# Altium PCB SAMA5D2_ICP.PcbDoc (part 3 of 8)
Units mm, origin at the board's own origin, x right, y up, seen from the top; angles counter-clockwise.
Board outline 150 x 100 mm, 6 copper layers (L1 - TOP, L2 - GND, L3 - SIG, L4 - SIG, L5 - VCC, L6 - BOT), stack 1.512 mm thick; 708 components, 597 nets, 2710 pads, 1437 vias.
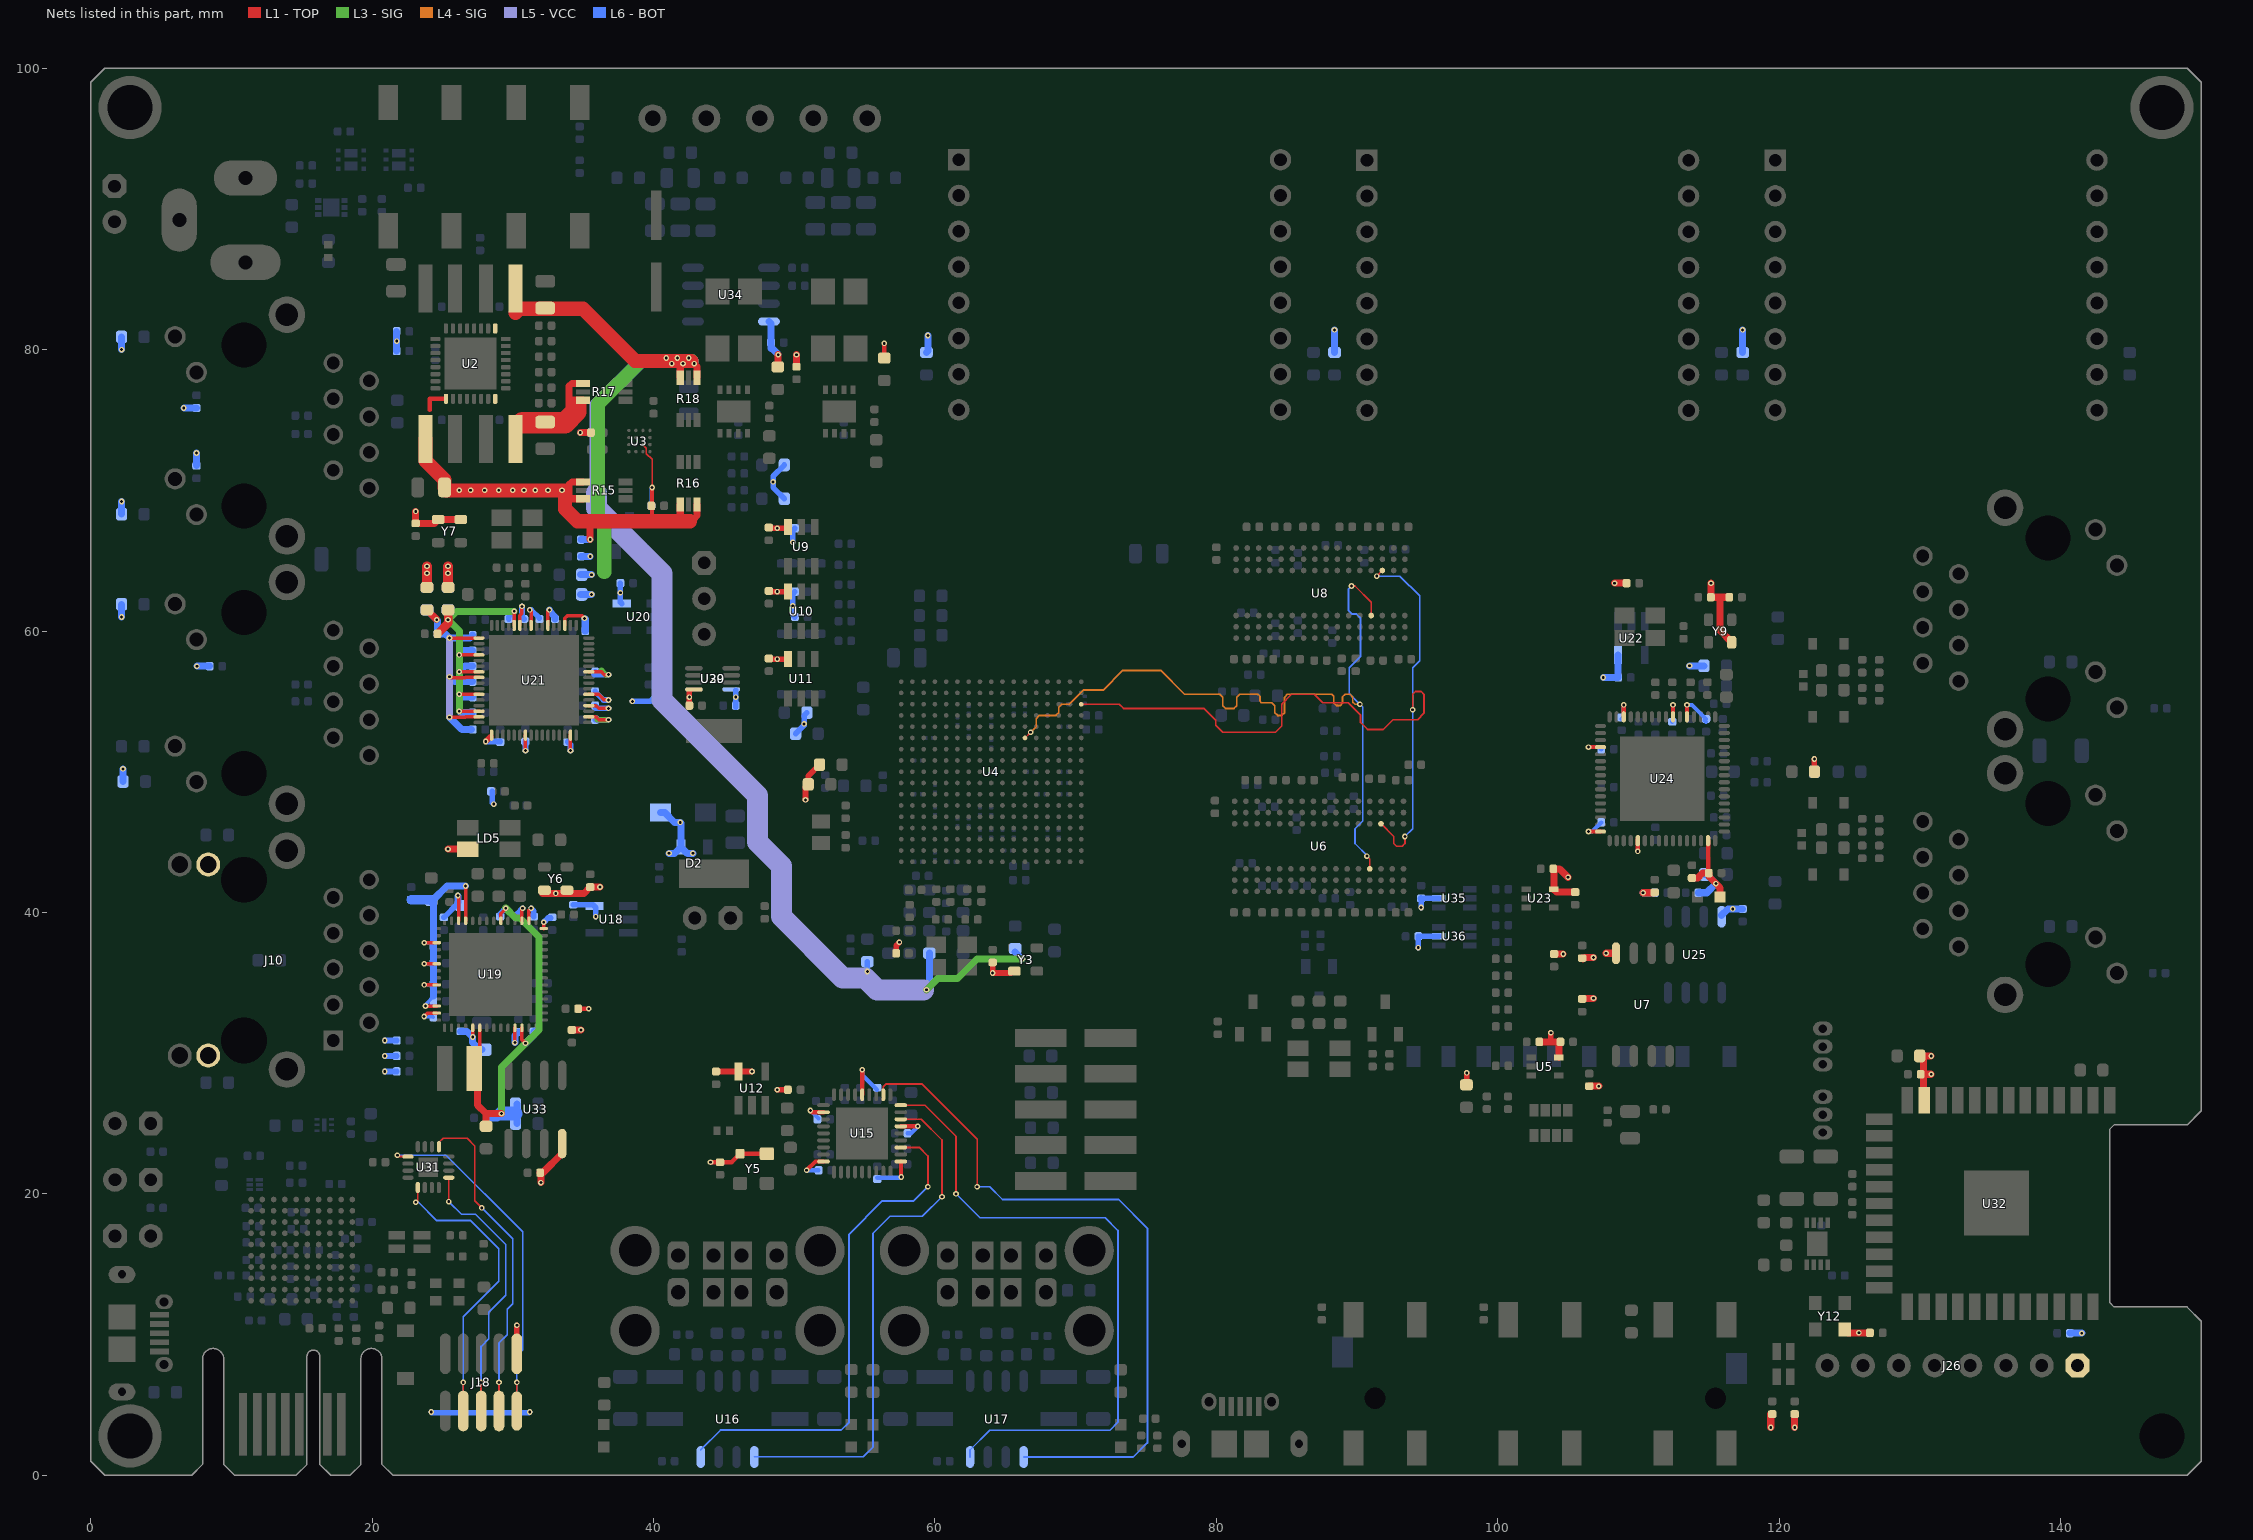
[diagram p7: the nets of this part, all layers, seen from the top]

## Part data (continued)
C282 C283 C295 C296: library part CAP1558, "Capacitor", Manufacturer 1=Yageo, Manufacturer 2="Taiyo Yuden", Manufacturer Part Number 1=CC1210MKX5R7BB107, Manufacturer Part Number 2=EMK325ABJ107MM-T, Operating Temperature="-55C to +85C", Package=1210, Supplier Part Number 1=311-2052-2-ND, Temperature Coeffcient=X5R, Tolerance=20%, Voltage=16V
C284 C285 C297 C298: library part CAP0507, "Capacitor", Manufacturer 1=KEMET, Manufacturer Part Number 1=C1206C476M8PACTU, Operating Temperature="-55C to +125C", Package=1206, Supplier Part Number 1=399-5508-2-ND, Temperature Coeffcient=X5R, Tolerance=20%, Voltage=10V
C290: library part CAP0546, "Capacitor", Manufacturer 1=Panasonic, Manufacturer Part Number 1=EEE-1AA221XP, Operating Temperature="-40C to +85C", Package=AL-D8, Supplier Part Number 1=PCE3871CT-ND, Tolerance=20%, Voltage=10V
C302 C303 C305: library part CAP0597, "Capacitor", Manufacturer 1=TDK, Manufacturer Part Number 1=C1608X5R1C225K, Operating Temperature="-55C to +85C", Package=0603, Supplier Part Number 1=445-5157-1-ND, Temperature Coeffcient=X5R, Tolerance=10%, Voltage=16V
C304: library part CAP0566, "Capacitor", Manufacturer 1=TDK, Manufacturer Part Number 1=C1005C0G1E102J, Operating Temperature="-55C to +125C", Package=0402, Supplier Part Number 1=445-2651-1-ND, Temperature Coeffcient=C0G, Tolerance=5%, Voltage=25V
D1: library part DIODE1357, "DIO SCTKY RB160M-60TR 550mV 1A 60V SMD SOD-123F", Forward Current=1A, Manufacturer 1="Rohm Semiconductor", Manufacturer Part Number 1=RB160M-60TR, Operating Temperature="-40C to +150C", Package=SOD-123-2, Power=1W, Reverse Current=50uA, Reverse Voltage=60V, Supplier Part Number 1=755-RB160M-60TR
D2: library part DIODE0101, Forward Current=200mA, Manufacturer 1=Fairchild, Manufacturer Part Number 1=BAT54C, Operating Temperature="-55C to +150C", Package=SOT-23-3, Power=290mW, Reverse Current=2uA, Reverse Voltage=30V, Supplier Part Number 1=BAT54CFSTR-ND
D3 D4: library part DIODE1426, "LED", Forward Current=1mA, Manufacturer 1="Rohm Semiconductor", Manufacturer Part Number 1=SML-P11VTT86, Operating Temperature="-40C to +85C", Package=0402, Power=50mW, Reverse Current=10uA, Reverse Voltage=5V, Supplier Part Number 1=511-1654-1-ND
D9: library part DIODE1309, "LED", Forward Current=20mA, Manufacturer 1="Wurth Electronics Inc", Manufacturer Part Number 1=150060GS75000, Operating Temperature="-40C to +85C", Package=0603, Supplier Part Number 1=732-4971-1-ND
D10: library part DIODE1254, "DIO SCTKY RB160M-60TR 550mV 1A 60V SMD SOD-123F", Forward Current=1A, Manufacturer 1="NXP Semiconductors                                                                               NXP Semiconductors", Manufacturer Part Number 1=PMEG6010ER,115, Operating Temperature="-65C to +150C", Package=SOD-123, Power=0.95W, Reverse Current=60uA, Reverse Voltage=60V, Supplier Part Number 1=568-7412-1-ND
D11 D12 D13 D14 D15 D16 D17 D18: library part DIODE1008, "DIO SCTKY RB160M-60TR 550mV 1A 60V SMD SOD-123F", Forward Current=500mA, Manufacturer 1="Diodes Incorporated", Manufacturer Part Number 1=B0520WS-7-F, Operating Temperature="-55C to +125C", Package=SOD-323, Power=235mW, Reverse Current=250uA, Reverse Voltage=20V, Supplier Part Number 1=B0520WS-FDICT-ND
D19 D20 D21 D22: library part DIODE1322, Manufacturer 1="AVX Corporation", Manufacturer Part Number 1=GG040205170N2P, Operating Temperature=125°C, Package=0402, Power=80W, Reverse Voltage=5V, Supplier Part Number 1=478-10595-1-ND
FB1 FB2 FB3 FB4 FB5 FB6 FB7 FB8 FB9 FB10 FB11 FB12 FB13 FB14 FB18 FB20 FB21 FB26 FB27: library part IND1453, "FERRITE 180R 1.5A SMD 0603", Manufacturer 1="Murata Electronics North America", Manufacturer Part Number 1=BLM18PG181SN1D, Operating Temperature="-55C to +125C", Package=0603, Saturation Current=1.5A, Supplier Part Number 1=490-5263-1-ND, Test Frequency=100MHz
FB17 FB19 FB22 FB23 FB24 FB25: library part IND1025, "FERRITE 180R 1.5A SMD 0603", Manufacturer 1=Murata, Manufacturer Part Number 1=BLM18AG221SN1D, Package=SMD, RMS Current=500ma, Supplier Part Number 1=490-1012-1-ND, Test Frequency="100 MHz"
J1: library part CON1560, Manufacturer 1="MPD (Memory Protection Devices)", Manufacturer Part Number 1=EJ508A, Supplier Part Number 1=EJ508A-ND
J2 J3 J17 J19 J20: library part CON1108, Manufacturer 1=FCI, Manufacturer 4=Samtec, Manufacturer 5=Sullins, Manufacturer 6="SPC Technology", Manufacturer 8=Nextron, Manufacturer Part Number 1=77311-118-02LF, Manufacturer Part Number 2=68001-202HLF, Manufacturer Part Number 3=68000-202HLF, Manufacturer Part Number 4=TSW-102-07-G-S, Manufacturer Part Number 5=PBC02SAAN, Manufacturer Part Number 6=SPC20481, Manufacturer Part Number 7=TSW-102-07-F-S, Manufacturer Part Number 8=R-211-0211-0021-000, Manufacturer Part Number 9=TSW-102-07-S-S, Supplier Part Number 1=609-4434-ND
J4 J25: library part CON1345, Manufacturer 1=Samtec, Manufacturer Part Number 1=TMS-103-01-G-S
J5: library part CON1752, Current=500mA, Manufacturer 1="Amphenol FCI", Manufacturer Part Number 1=10067847-001RLF, Supplier Part Number 1=609-3956-1-ND, Voltage=17V
J6: library part CON1693, Current=13.5A, Manufacturer 1="Phoenix Contact", Manufacturer Part Number 1=1727049, Supplier Part Number 1=277-1950-ND, Voltage=300
J7 J8: library part CON1430, "Connector USB DUAL", Current=1.5A, Manufacturer 1="Assmann WSW Components", Manufacturer Part Number 1=AU-Y1008-2, Supplier Part Number 1=AE11131-ND
J9 J16: library part CON1753, "Connector USB Mini", Current="1A, 1.8A", Manufacturer 1="Molex, LLC", Manufacturer Part Number 1=0475890001, Supplier Part Number 1=WM17143CT-ND, Voltage=30VAC
J10: library part CON1767, Manufacturer 1="Pulse Electronics Network", Manufacturer Part Number 1=JD1-0001NL, Supplier Part Number 1=553-2361-ND
J11 J12 J13 J14: library part CON1769, Manufacturer 1="Pulse Electronics Network", Manufacturer Part Number 1=J00-0045NL, Supplier Part Number 1=553-1619-5-ND
J15: library part CON1674, "CON_PCB_MEC1-108-02-F-D-RA1-SL", Current=1.6A, Manufacturer 1="Samtec Inc.", Manufacturer Part Number 1=MEC1-108-02-F-D-RA1-SL, Supplier Part Number 1=SAM11473-ND
J18: library part CON1047, "CON HDR-1.27 Male 2x5 Gold 3.05MH SMD VERT", Manufacturer 1=Samtec, Manufacturer Part Number 1=FTSH-105-01-F-DV-K
J21 J22 J23: library part SKT1042, Manufacturer 1="Sullins Connector Solutions", Manufacturer 2=Nextron, Manufacturer Part Number 1=PPTC081LFBN-RC, Manufacturer Part Number 2=R-212-0810-0071-000, Package="mikroBUS HOST", Supplier Part Number 1=S7006-ND
J24: library part CON1639, "CON HDR-1.27 Male 2x5 Gold 3.05MH SMD VERT", Current=4.1A, Manufacturer 1="Samtec Inc.", Manufacturer Part Number 1=TSM-105-01-T-DV, Supplier Part Number 1=SAM8985-ND, Voltage=475V
J26: library part CON1302, "CON HDR-2.54 Female 1x8 Gold TH", Manufacturer 1=FCI, Manufacturer 2=Nextron, Manufacturer Part Number 1=68001-108HLF, Manufacturer Part Number 2=211-081A7-0021-400, Manufacturer Part Number 3=R-211-0611-0021-400, Supplier Part Number 1=609-3273-ND
J27: library part CON1105, Manufacturer 1=FCI, Manufacturer 2=Nextron, Manufacturer Part Number 1=68000-103HLF, Manufacturer Part Number 2=R-211-0311-0021-000, Supplier Part Number 1=609-3461-ND
L1 L2 L3 L4: library part IND1590, Manufacturer 1="TDK Corporation", Manufacturer Part Number 1=VLS3012HBX-1R5M, Operating Temperature="-40C to +105C", Package=1212, RMS Current=4.19A, Saturation Current=4.41A, Supplier Part Number 1=445-175068-1-ND, Test Frequency=1MHz
L5 L6 L7: library part IND1213, Manufacturer 1="TDK Corporation", Manufacturer Part Number 1=MLZ1608N100LT000, Supplier Part Number 1=445-6755-1-ND
L8 L9: library part IND1156, "Inductor", Manufacturer 1="EPCOS Inc", Manufacturer Part Number 1=B82789S223N2, Operating Temperature="-55C to +125C", Package="SIMDAD 1812", RMS Current=250mA, Supplier Part Number 1=495-4411-1-ND
L10: library part IND1587, Manufacturer 1="Bourns Inc.", Manufacturer Part Number 1=SRN3015TA-3R3M, Operating Temperature="-40C to +125C", Package=3mmx3mmx1.5mm, RMS Current=1.4A, Supplier Part Number 1=SRN3015TA-3R3MCT-ND, Test Frequency=100KHz
LABEL1: library part 08-00028
LD1 LD2 LD3 LD4: library part DIODE1155, "LED", Forward Current=30mA, Manufacturer 1="Lite-On Inc", Manufacturer 2=Ledtech, Manufacturer Part Number 1=LTST-C191KGKT, Manufacturer Part Number 2=LT8A23-54-SB96-T5, Operating Temperature="-55C to +85C", Power=75mW, Reverse Voltage=5V, Supplier Part Number 1=160-1446-1-ND
LD5: library part DIODE1214, Forward Current="20mA, 20mA, 20mA", Manufacturer 1="Cree Inc", Manufacturer 2="Cree Inc.", Manufacturer Part Number 1=CLV1A-FKB-CK1N1G1BB7R4S3, Manufacturer Part Number 2=CLV1A-FKB-CK1VW1DE1BB7C3C3, Operating Temperature="-40C - +100C", Package=4-PLCC, Power="130mW, 100mW, 100mW", Reverse Current=10uA, Reverse Voltage=5V, Supplier Part Number 1=CLV1A-FKB-CK1N1G1BB7R4S3CT-ND
LD6 LD8: library part DIODE1110, "LED", Forward Current=30mA, Manufacturer 1="Kingbright Corp", Manufacturer Part Number 1=APHBM2012SURKCGKC, Operating Temperature="-40C to +85C", Package=0805, Power=75mW, Reverse Current=10uA, Supplier Part Number 1=754-1093-1-ND
LD7: library part DIODE1214, Forward Current="20mA, 20mA, 20mA", Manufacturer 1="Cree Inc", Manufacturer Part Number 1=CLV1A-FKB-CK1N1G1BB7R4S3, Operating Temperature="-40C - +100C", Package=4-PLCC, Power="130mW, 100mW, 100mW", Reverse Current=10uA, Reverse Voltage=5V, Supplier Part Number 1=CLV1A-FKB-CK1N1G1BB7R4S3CT-ND
Q1 Q2: library part TRA1245, Current=-4.5A, Drain to Source Voltage=-20V, Gate to Source Voltage=900mV, Manufacturer 1="Vishay Siliconix", Operating Temperature="-55C to +150C", Package=SC70-6L, Power=7.8W, Supplier Part Number 1=SIA923AEDJ-T1-GE3CT-ND
Q3 Q4 Q5 Q6: library part TRA1223, "Transistor MOS", Current=230mA, Drain to Source Voltage=60V, Gate to Source Voltage=20V, Manufacturer 1="Infineon Technologies", Manufacturer Part Number 1=BSS138NH6327XTSA2, Operating Temperature="-55C to +150C", Package=SOT23-3, Power=0.36W, Supplier Part Number 1=BSS138NH6327XTSA2CT-ND
R1 R2 R12 R23 R24 R66 R80 R83 R84 R88 R91 R97 R98 R102 R103 R104 R107 R111 R113 R131 R132 R134 R150 R151 R153 R167 R171 R172 R175 R177 R180 R181 R199 R208 R217 R220 R242 R243 R249 R256 R261 R262 R263 R264 R265 R268 R271: library part RSMT1019, Manufacturer 1=Panasonic, Manufacturer Part Number 1=ERJ-2RKF1002X, Operating Temperature="-55C to +155C", Package=0402, Power=1/10W, Supplier Part Number 1=P10.0KLCT-ND, Temperature Coeffcient=100ppm/C, Tolerance=1%, Voltage=50V
R3: library part RSMT0021, Manufacturer 1="Stackpole Electronics Inc.", Manufacturer 2=Panasonic, Manufacturer 3=Yageo, Manufacturer 4=ROHM, Manufacturer 5="Stackpole Electronics Inc", Manufacturer Part Number 1=RMCF0805JT100R, Manufacturer Part Number 2=ERJ-6GEYJ101V, Manufacturer Part Number 3=9C08052A1000JLHFT, Manufacturer Part Number 4=MCR10EZHJW100E, Manufacturer Part Number 5="RMCF 1/10 100 1%", Manufacturer Part Number 6=9C08052A1000JLPFT, Operating Temperature="-55C to +155C", Package=0805, Power=1/8W, Supplier Part Number 1=RMCF0805JT100RCT-ND, Temperature Coeffcient=100ppm/C, Tolerance=5%, Voltage=150V
R4 R5 R7 R8 R9 R10 R22 R68 R69 R70 R71 R75 R86 R87 R94 R95 R146 R147 R165 R166 R169 R170 R184 R185: library part RSMT1040, Manufacturer 1=Yageo, Manufacturer Part Number 1=RC0402JR-070RL, Operating Temperature="-55C to +155C", Package=0402, Power=1/16W, Supplier Part Number 1=311-0.0JRCT-ND
R6 R82 R124 R136 R137 R152 R164 R173 R216 R244 R245: library part RSMT0138, Manufacturer 1=Panasonic, Manufacturer 2=Yageo, Manufacturer 3=ROHM, Manufacturer 4="Stackpole Electronics Inc", Manufacturer 6=Vishay, Manufacturer 8="TE Connectivity", Manufacturer Part Number 1=ERJ-3EKF1001V, Manufacturer Part Number 2=RC0603FR-071KL, Manufacturer Part Number 3=MCR03EZPFX1001, Manufacturer Part Number 4=RMCF0603FT1K00, Manufacturer Part Number 5="RMCF 1/16 1K 1% R", Manufacturer Part Number 6=CRCW06031K00FKEA, Manufacturer Part Number 7=RMCF1/161.0K1%TR, Manufacturer Part Number 8=1622866-1, Operating Temperature="-55C to +155C", Package=0603, Power=1/10W, Supplier Part Number 1=P1.00KHCT-ND, Temperature Coeffcient=100ppm/C, Tolerance=1%, Voltage=75V
R11 R13 R65 R72 R89 R120 R121 R122 R123 R130 R178 R207 R211 R212 R213: library part RES1011, Manufacturer 1=Panasonic, Manufacturer Part Number 1=ERJ-2RKF1003X, Operating Temperature="-55C to +125C", Package=0402, Power=1/10W, Supplier Part Number 1=P100KLCT-ND, Temperature Coeffcient=100ppm/C, Tolerance=1%, Voltage=50V
R14 R25 R26 R42 R43 R44 R45 R46 R47 R138 R246: library part RES1130, Manufacturer 1=Panasonic, Manufacturer Part Number 1=ERJ-3EKF2201V, Operating Temperature="-55C to +155C", Package=0603, Power=1/10W, Supplier Part Number 1=P2.20KHCT-ND, Temperature Coeffcient=100ppm/C, Tolerance=1%, Voltage=75V
R15 R16 R17 R18: library part RSMT1231, "Shunt", Current=5A, Manufacturer 1=Yageo, Manufacturer Part Number 1=PF1206FRF070R01L, Operating Temperature="-55C to +155C", Package=1206, Power=1/4W, Supplier Part Number 1=311-0.01AJCT-ND, Temperature Coeffcient=100ppm/C, Tolerance=1%, Voltage=50mV
R19 R20 R21: library part RSMT1138, Manufacturer 1="Stackpole Electronics Inc", Manufacturer Part Number 1=RMCF0603JT2R20, Supplier Part Number 1=RMCF0603JT2R20CT-ND
R27 R28 R29 R30 R31 R32 R33 R34 R35 R36 R37 R38 R39 R40 R41 R48 R49 R50 R51 R52 R53 R54 R55 R56 R57 R58 R59 R60 R61 R62 R63 R269 R270: library part RES1474, Manufacturer 1="Panasonic Electronic Components", Manufacturer Part Number 1=ERJ-2RKF22R0X, Operating Temperature="-55C to +155C", Package=0402, Power=1/10W, Supplier Part Number 1=P22.0LCT-ND, Temperature Coeffcient=100ppm/C, Tolerance=1%
R64: library part RES1900, Current=1A, Manufacturer 1=Yageo, Manufacturer Part Number 1=RC0402FR-0723K2L, Operating Temperature="-55C to +155C", Package=0402, Power=1/16W, Supplier Part Number 1=YAG3066CT-ND, Temperature Coeffcient=100ppm/C, Tolerance=1%, Voltage=50V
R67: library part RES1623, Manufacturer 1=Samsung, Manufacturer Part Number 1=RC1005F1692CS, Operating Temperature="-55C to +155C", Package=0402, Power=1/16W, Supplier Part Number 1=1276-4133-1-ND, Tolerance=1%, Voltage=50V
R76 R77: library part RES1659, Current=1A, Manufacturer 1="Yageo                                                                                               Yageo", Manufacturer Part Number 1=RC0402FR-071RL, Operating Temperature="-55C to 155C", Package=0402, Power=1/16W, Supplier Part Number 1=311-1.00LRCT-ND, Temperature Coeffcient=200ppm/°C, Tolerance=1%, Voltage=50V
R78: library part RES2053, Manufacturer 1=Yageo, Manufacturer Part Number 1=RC0201FR-075K62L, Operating Temperature="-55C to +125C", Package=0201, Power=1/20W, Supplier Part Number 1=YAG2345CT-ND, Temperature Coeffcient=200ppm/C, Tolerance=1%
R79: library part RES1581, Current=0.5A, Manufacturer 1="Panasonic Electronic Components", Manufacturer Part Number 1=ERJ-1GE0R00C, Operating Temperature="-55°C to 125°C", Package=0201, Supplier Part Number 1=P0.0AGCT-ND
R85 R92: library part RES1897, Current=1A, Manufacturer 1=Yageo, Manufacturer Part Number 1=RC0402FR-07240RL, Operating Temperature="-55C to +155C", Package=0402, Power=1/16W, Supplier Part Number 1=311-240LRCT-ND, Temperature Coeffcient=100ppm/C, Tolerance=1%, Voltage=50V
R101: library part RNET1004, "Resistor", Current=1A, Manufacturer 1=Yageo, Manufacturer Part Number 1=YC164-JR-0768KL, Operating Temperature="-55C to +155C", Package=1206, Power=62.5mW, Supplier Part Number 1=YC164J-68KCT-ND, Temperature Coeffcient=200ppm/C, Tolerance=5%, Voltage=50V
R106 R109 R110 R140 R141 R142 R143 R183 R189 R191 R192 R209 R227 R228 R229 R230 R231 R234 R235 R236 R237 R238 R248 R255: library part RSMT0001, Manufacturer 1=Panasonic, Manufacturer 3=ROHM, Manufacturer 4="Stackpole Electronics Inc", Manufacturer 6=Vishay, Manufacturer 7=Yageo, Manufacturer 8="KOA Speer", Manufacturer 9="NIC Components", Manufacturer Part Number 1=ERJ-3GSY0R00V, Manufacturer Part Number 2=ERJ-3GEY0R00V, Manufacturer Part Number 3=MCR03EZPJ000, Manufacturer Part Number 4=RMCF0603ZT0R00, Manufacturer Part Number 5="RMCF 1/16 0 R", Manufacturer Part Number 6=CRCW06030000Z0EA, Manufacturer Part Number 7=RC0603JR-070RL, Manufacturer Part Number 8=RK73Z1JTTP, Manufacturer Part Number 9=NRC06Z0TRF, Operating Temperature="-55C to +155C", Package=0603, Power=1/10W, Supplier Part Number 1=P0.0GTR-ND
R108 R135 R148 R168 R202: library part RES1384, Manufacturer 1=Yageo, Manufacturer Part Number 1=RC0603FR-0751RL, Operating Temperature="–55C to +155C", Package=0603, Power=1/10W, Supplier Part Number 1=311-51.0HRTR-ND, Temperature Coeffcient=100ppm/C, Tolerance=1%, Voltage=50V
R112 R133: library part RES1021, Manufacturer 1="Rohm Semiconductor", Manufacturer Part Number 1=MCR01MZPF1202, Operating Temperature="-55C to +155C", Package=0402, Power=1/16W, Supplier Part Number 1=RHM12.0KLCT-ND, Temperature Coeffcient=400ppm/C, Tolerance=1%, Voltage=50V
R114 R115 R116 R117 R118 R119: library part RSMT1232, Current=90mA, Manufacturer 1="Panasonic Electronic Components", Manufacturer Part Number 1=ERJ-P06J620V, Operating Temperature="-55C to +155C", Package=0805, Power=1/2W, Supplier Part Number 1=P62ADCT-ND, Temperature Coeffcient=200ppm, Tolerance=5%, Voltage=600V
R125 R126 R127 R128: library part RSMT0206, Manufacturer 1=Panasonic, Manufacturer Part Number 1=ERJ-3GEYJ151V, Operating Temperature="-55C to +155C", Package=0603, Power=1/10W, Supplier Part Number 1=P150GTR-ND, Temperature Coeffcient=200ppm/C, Tolerance=5%, Voltage=75V
R129: library part RES1424, Manufacturer 1=Panasonic, Manufacturer Part Number 1=ERJ-2RKF2003X, Operating Temperature="-55C to +125C", Package=0402, Power=1/10W, Supplier Part Number 1=P200KLCT-ND, Temperature Coeffcient=100ppm/C, Tolerance=1%, Voltage=50V
R139: library part RES1437, Manufacturer 1="Panasonic Electronic Components", Manufacturer Part Number 1=ERJ-2RKF2001X, Operating Temperature="-55°C ~ 155°C", Package=0402, Power=1/10W, Supplier Part Number 1=P2.00KLCT-ND, Temperature Coeffcient=±100ppm/°C, Tolerance=1%
R144 R145: library part RES1205, Manufacturer 1=Panasonic, Manufacturer Part Number 1=ERJ-3EKF68R0V, Operating Temperature="-55C to +155C", Package=0603, Power=1/10W, Supplier Part Number 1=P68.0HCT-ND, Temperature Coeffcient=100ppm/C, Tolerance=1%, Voltage=75V
R149: library part RES1495, Manufacturer 1="Rohm Semiconductor", Manufacturer Part Number 1=MCR01MRTF6041, Operating Temperature="-55C to +155C", Package=0402, Power=1/16W, Supplier Part Number 1=RHM6.04KCDTR-ND, Tolerance=1%, Voltage=50V
R155 R156 R157 R176 R179 R259 R266 R267: library part RSMT0734, Manufacturer 1=Panasonic, Manufacturer 2=Yageo, Manufacturer Part Number 1=ERJ-2GEJ472X, Manufacturer Part Number 2=RC0402JR-074K7L, Operating Temperature="-55C to +155C", Package=0402, Power=1/10W, Supplier Part Number 1=P4.7KJCT-ND, Temperature Coeffcient=200ppm/C, Tolerance=5%, Voltage=50V
R158 R159 R160 R161 R224 R225 R226 R232 R233: library part RSMT0166, Manufacturer 1=Panasonic, Manufacturer 2="KOA Speer", Manufacturer 3="Stackpole Electronics Inc", Manufacturer Part Number 1=ERJ-3GEYJ331V, Manufacturer Part Number 2=RK73B1JTTD331J, Manufacturer Part Number 3="RMCF 1/16 330 5% R", Operating Temperature="-55C to +155C", Package=0603, Power=1/10W, Supplier Part Number 1=P330GTR-ND, Temperature Coeffcient=200ppm/C, Tolerance=5%, Voltage=75V
R162 R198: library part RSMT0003, Current=2A, Manufacturer 1=Panasonic, Manufacturer 2="KOA Speer", Manufacturer 3=Bourns, Manufacturer Part Number 1=ERJ-8GEY0R00V, Manufacturer Part Number 2=RK73Z2BTTD, Manufacturer Part Number 3=CR1206-J/-000ELF, Package=1206, Supplier Part Number 1=P0.0ETR-ND
R174: library part RES1490, Manufacturer 1="Rohm Semiconductor", Manufacturer Part Number 1=MCR01MRTF1212, Operating Temperature="-55C to +155C", Package=0402, Power=1/16W, Supplier Part Number 1=RHM12.1KCDCT-ND, Tolerance=1%, Voltage=50V
R182 R188 R190 R193 R194 R195 R197 R260: library part RES1498, Manufacturer 1="Panasonic Electronic Components", Manufacturer Part Number 1=ERA-2AEB49R9X, Package=0402, Power=1/16W, Supplier Part Number 1=P49.9DCCT-ND, Temperature Coeffcient=25ppm/C, Tolerance=0.1%
R200 R201 R210 R218 R219 R239 R240 R241 R250 R251 R252 R254 R257 R258: library part RES1436, Manufacturer 1="Panasonic Electronic Components", Manufacturer Part Number 1=ERJ-2RKF1000X, Operating Temperature="-55°C ~ 155°C", Package=0402, Power=1/10W, Supplier Part Number 1=P100LCT-ND, Temperature Coeffcient=±100ppm/°C, Tolerance=1%
R203 R204: library part RES1800, Manufacturer 1=Yageo, Manufacturer 2=Digi-Key, Manufacturer Part Number 1=RC0402FR-0739RL, Manufacturer Part Number 2=311-39.0LRCT-ND, Operating Temperature="-55°C ~ 155°C", Package=0402, Power=1/16W, Tolerance=1%
R205: library part RSMT0730, Manufacturer 1=Panasonic, Manufacturer 2=Vishay, Manufacturer Part Number 1=ERJ-2GE0R00X, Manufacturer Part Number 2=CRCW04020000Z0ED, Operating Temperature="-55C to +155C", Package=0402, Power=1/10W, Supplier Part Number 1=P0.0JCT-ND
R206: library part RSMT1211, Manufacturer 1="Vishay Dale", Manufacturer Part Number 1=CRCW04026K80FKED, Operating Temperature="-55C to +155C", Package=0402, Power=1/16W, Supplier Part Number 1=541-6.80KLCT-ND, Temperature Coeffcient=100ppm/C, Tolerance=1%, Voltage=50V
R214: library part RES1008, Manufacturer 1="Panasonic - ECG", Manufacturer Part Number 1=ERJ-2GEJ221X, Operating Temperature="-55C to +155C", Package=0402, Power=1/10W, Supplier Part Number 1=P220JTR-ND, Temperature Coeffcient=200ppm/C, Tolerance=5%, Voltage=50V
R215 R221 R222 R223: library part RSMT1167, Manufacturer 1="Vishay Dale", Manufacturer Part Number 1=CRCW0402150RFKED, Supplier Part Number 1=541-150LCT-ND
R247: library part RES2196, Manufacturer 1=Yageo, Manufacturer Part Number 1=RC0402JR-07100KL, Package=0402, Power=1/16W, Supplier Part Number 1=311-100KJRCT-ND, Temperature Coeffcient=100ppm/C, Tolerance=5%
SW1 SW2 SW3 SW4 SW5: library part SWITCH0077, "Switch", Current=50mA, Manufacturer 1=E-Switch, Manufacturer 2="Switech Electronics Co. Ltd", Manufacturer Part Number 1=TL3301AF260QG, Manufacturer Part Number 2=TS2A-050C-G-GP, Operating Temperature="-20C to +70C", Supplier Part Number 1=EG2527CT-ND, Voltage=12V
U1: library part IC1481, Manufacturer 1="ON Semiconductor", Manufacturer Part Number 1=NCP349MNAETBG, Operating Temperature="-40C to 85C", Package=DFN-6, Supplier Part Number 1=NCP349MNAETBGOSCT-ND
U2: library part "MCP16502 QFN-32", "QFN-32", Manufacturer 1=Microchip, Manufacturer Part Number 1=MCP16502AA-E/S8
U3: library part MIC7499, Manufacturer 1="Microchip Technology", Manufacturer Part Number 1=PAC1934T-I/J6CX
U4: library part MIC7216, Manufacturer 1="Microchip Technology", Manufacturer Part Number 1=ATSAMA5D27C-CU, PackageType=LFBGA, PackageWidth=14x14x1.4mm, Supplier Part Number 1=ATSAMA5D27C-CU-ND, TempRange="-40C to +85C"
U5: library part IC1434, Manufacturer 1="ON Semiconductor", Manufacturer Part Number 1=NL17SZ126DFT2G, Operating Temperature="-40C to +125C", Package=SOT-353, Supplier Part Number 1=NL17SZ126DFT2GOSCT-ND
U6 U8: library part IC1526, Manufacturer 1="Winbond Electronics", Manufacturer Part Number 1=W632GU6MB-12, Operating Temperature="0C to +95C", Package=96-TFBGA, Supplier Part Number 1=W632GU6MB-12-ND
U7: library part MIC6216, "SQI Serial Flash", Manufacturer 1="Microchip Technology", Manufacturer Part Number 1=SST26VF064B-104I/SM, MaxClockFreq="104 MHz", OpVoltMax=3,6, OpVoltMin=2,3, PackageType=SOIJ, PackageWidth=.208in, TempRange="-40C to +85C"
U9 U10 U11: library part MIC7407, Manufacturer 1="Microchip Technology", Manufacturer Part Number 1=24AA025E48T-I/OT, MaxClockFreq="400 kHz", OpVoltMax=5.5, OpVoltMin=1.7, PackageType=SOT-23, Supplier Part Number 1=24AA025E48T-I/OTCT-ND, TempRange="-40C to +85C"
U12 U18 U20 U22: library part IC1056, "Gate AND", Manufacturer 1="Texas Instruments", Manufacturer Part Number 1=SN74LVC1G08DBVR, Operating Temperature="-40C to +85C", Package=SOT-23-5, Supplier Part Number 1=296-11601-2-ND
U13 U14: library part MIC7856, Manufacturer 1="Microchip Technology", Manufacturer Part Number 1=MCP2542FDT-E/MF, OperatingCurrentMax=10, OperatingVoltageMax=5.5, OperatingVoltageMin=4.5, PackageType=DFN, PackageWidth=3x3x0.9mm, StandbyCurrentMax=15, Supplier Part Number 1=MCP2542FDT-E/MFCT-ND, TempRange="-40C to +125C", TransientVoltage="-150 to +100"
U15: library part MIC7448, Manufacturer 1="Microchip Technology", Manufacturer Part Number 1=USB2534I-1080AEN, Supplier Part Number 1=USB2534I-1080AEN-ND
U16 U17: library part IC1155, Manufacturer 1="Micrel Inc", Manufacturer Part Number 1=MIC2026-1YM, Operating Temperature="-40C to +85C", Package=SOIC-8, Supplier Part Number 1=576-1059-2-ND
U19: library part MIC7437, Manufacturer 1="Microchip Technology", Manufacturer Part Number 1=LAN7850T-I/8JXCT-ND
U21: library part MIC7332, Manufacturer 1="Microchip Technology Inc", Manufacturer Part Number 1=KSZ8563RNXI
U23: library part IC1433, Manufacturer 1="ON Semiconductor", Manufacturer Part Number 1=NL17SZ125DFT2G, Operating Temperature="-55C to +125C", Package=SOT-353, Supplier Part Number 1=NL17SZ125DFT2GOSCT-ND
U24: library part MIC7449, Manufacturer 1="Microchip Technology", Manufacturer Part Number 1=LAN9252I/ML, Supplier Part Number 1=LAN9252I/ML-ND
U25: library part MIC7059, "EEPROM I2C", Manufacturer 1="Microchip Technology", Manufacturer Part Number 1=24FC512T-I/SN, MaxClockFreq="1 MHz", OpVoltMax=5,5, OpVoltMin=1,7, PackageType=SOIC, PackageWidth=3.90mm(.150in), Supplier Part Number 1=24FC512T-I/SN-ND, TempRange="-40C to +85C"
U26: library part MIC6905, Manufacturer 1="Microchip Technology", Manufacturer Part Number 1=MIC5528-3.3YMT-TR, PackageType=UDFN, PackageWidth=1.2x1.2x0.6mm, Supplier Part Number 1=576-4766-1-ND, TempRange="-40C to +125C"
U27: library part MIC7470, Manufacturer 1="Microchip Technology", Manufacturer Part Number 1=ATSAM3U4CA-CU, PackageType=TFBGA, PackageWidth=9x9x1.2mm, Supplier Part Number 1=ATSAM3U4CA-CU-ND, TempRange="-40C to +85C"
U28: library part IC1519, "SWITCH SPDT", Manufacturer 1="ON Semiconductor", Manufacturer Part Number 1=NLAS3157MX3TCG, Operating Temperature="-40C to +85C", Package=ULLGA-6, Supplier Part Number 1=NLAS3157MX3TCGOSCT-ND
U29: library part IC1512, "BUFFER DL TRI-ST NON-INV", Manufacturer 1="ON Semiconductor", Manufacturer Part Number 1=NL27WZ125USG, Operating Temperature="-55C to +125C", Package=US-8, Supplier Part Number 1=NL27WZ125USGOSCT-ND
U30: library part IC1514, "BUFFER DL TRI-ST NON-INV", Manufacturer 1="ON Semiconductor", Manufacturer Part Number 1=NL27WZ126USG, Operating Temperature="-55C to +125C", Package=US-8, Supplier Part Number 1=NL27WZ126USGOSCT-ND
U31: library part IC1436, "IC SWITCHER NLAS3899B Analog Switch QFN16", Manufacturer 1="ON Semiconductor", Manufacturer Part Number 1=NLAS3899BMNTWG, Operating Temperature="-65C to +150C", Package=QFN16, Supplier Part Number 1=863-NLAS3899BMNTWG
U32: library part MIC7405, FrequencyRange="2.412-2.472 MHz", Manufacturer 1="Microchip Technology", Manufacturer Part Number 1=ATWILC3000-MR110CA, RfPower=0, Supplier Part Number 1=ATWILC3000-MR110CA-ND
U33: library part MIC6147, Manufacturer 1=Microchip, Manufacturer Part Number 1=93AA66A-I/SN, MaxClockFreq="2 MHz", OpVoltMax=5.5, OpVoltMin=1.8, PackageType=SOIC, PackageWidth=3.90mm(.150in), Supplier Part Number 1=579-93AA66A-I/SN, TempRange="-40C to +85C"
U34: library part MIC7054, Manufacturer 1="Microchip Technology", Manufacturer Part Number 1=ATECC608A-SSHDA-B
U35 U36: library part IC1149, Manufacturer 1="Texas Instruments", Manufacturer Part Number 1=SN74LVC1G3157DCKR, Operating Temperature="-40C to +85C", Package=SC-70-6, Supplier Part Number 1=296-14909-1-ND
U37: library part MIC2599, "LDO", Manufacturer 1=Microchip, Manufacturer Part Number 1=MCP1725T-3302E/MC, Manufacturer Part Number 2=MCP1725-3302E/MC, PackageType=DFN, PackageWidth=2x3x0.9mm, TempRange="-40C to +125C"
Y1: library part OSC1092, "Crystal", Load Capacitance=12.5pF, Manufacturer 1=NDK, Manufacturer Part Number 1=NX2012SA-32.768K-STD-MUB-1, Supplier Part Number 1=644-1219-1-ND, Tolerance=±20ppm
Y3: library part MIC8807, Manufacturer 1="Microchip Technology", Manufacturer Part Number 1=DSC1001DL5-012.0000, Supplier Part Number 1=DSC1001DL5-012.0000-ND
Y4: library part OSC1067, "Crystal", Load Capacitance=12pF, Manufacturer 1="AVX Corp/Kyocera Corp", Manufacturer 3="Interquip Electronics (Shenzhen) Company Limited", Manufacturer 4="Siward Crystal Technology Co. Ltd.", Manufacturer Part Number 1=CX3225SB12000H0FLJCC, Manufacturer Part Number 2=CX3225SB12000H0PSTC1, Manufacturer Part Number 3=5YAA12000121HFA0Q1, Manufacturer Part Number 4=XTL571100-H201-345, Supplier Part Number 1=1253-1734-1-ND
Y5: library part MIC7861, Manufacturer 1="Microchip Technology", Manufacturer Part Number 1=DSC1001CI5-024.0000, Supplier Part Number 1=576-4617-ND
Y6 Y7 Y9: library part MIC8282, Manufacturer 1="Microchip Technology", Manufacturer Part Number 1=DSC1001DI5-025.0000, Supplier Part Number 1=576-4982-5-ND
Y8 Y10: library part OSC1159, "Crystal", Load Capacitance=20pF, Manufacturer 1="ECS Inc.", Manufacturer Part Number 1=ECS-250-20-33-CKM-TR, Operating Temperature="-20C to +70C", Package=L3.2W2.5H0.8, Supplier Part Number 1=XC1817CT-ND, Tolerance=10ppm
Y11: library part MIC7210, Manufacturer 1="Microchip Technology Inc", Manufacturer Part Number 1=DSC6011JI1A-012.0000
Y12: library part MIC7476, Manufacturer 1="Microchip Technology", Manufacturer Part Number 1=DSC6083CE2A-032K768, Supplier Part Number 1=DSC6083CE2A-032K768-ND

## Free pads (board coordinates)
  round 4.5 hole 3.2 unplated mask+0.05: 0(2.8,2.8) 0(2.8,97.2) 0(147.2,97.2)
  round 0 hole 3.2 unplated mask+0.05: 0(147.2,2.8)

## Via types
v1: diameter 0.4, hole 0.2, L1 - TOP to L6 - BOT, tented both sides, 1312 vias
v2: diameter 0.55, hole 0.3, L1 - TOP to L6 - BOT, 84 vias
v3: diameter 0.4, hole 0.2, L1 - TOP to L6 - BOT, tented top, 25 vias
v4: diameter 0.55, hole 0.3, L1 - TOP to L6 - BOT, tented bottom, 16 vias

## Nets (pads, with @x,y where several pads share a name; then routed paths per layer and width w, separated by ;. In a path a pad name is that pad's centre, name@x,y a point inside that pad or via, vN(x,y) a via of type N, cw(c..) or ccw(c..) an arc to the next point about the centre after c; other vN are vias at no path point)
1V2_LAN: C160.2 C179.2 C180.2 C249.2 FB18.1 FB20.1 L10.2 U19.20 U19.26 U19.48 | length 33.7
  L1 - TOP w0.25: L10.2@27.65,28.3 U19.20@27.65,31.8 ; U19.48@29.15,39.4 29.15,39.905 29.5,40.255 v1(29.5,40.3) ; U19.26@30.65,31.8 30.65,30.95 v1(30.9,30.7)
  L1 - TOP w0.5: L10.2@27.25,28.9 27.5,28.65 27.5,26.3 28.1,25.7 ; C160.2@28.1,24.8 28.1,25.7 ; v1(29.2,25.7) 28.1,25.7
  L3 - SIG w0.5: v1(29.2,25.7) 29.2,29 v1(30.9,30.7) 31.85,31.65 31.85,38.255 30.505,39.6 30.2,39.6 v1(29.5,40.3)
  L6 - BOT w0.25: C179.2@29.1,39.605 C179.2@29.1,39.7 C179.2@29.1,39.9
  L6 - BOT w0.4: C179.2@29.1,39.9 v1(29.5,40.3)
  L6 - BOT w0.5: C249.2@28.15,25.4 28.9,25.4 v1(29.2,25.7) ; FB18.1@30.3,25 FB20.1@30.3,26.4 ; v1(30.9,30.7) 31.5,31.3 C180.2@31.5,31.55
  L6 - BOT w1: v1(29.2,25.7) 30.2,25.7
1V25: C16.1 C188.2 C193.2 C203.2 C205.2 C207.2 C209.2 C211.2 C212.2 FB1.1 FB2.1 FB19.1 L3.2 R18.1 R19.1 U2.25 U21.17 U21.31 U21.34 U21.42 U21.54 U21.59 | length 128.8
  L1 - TOP w0.25: U21.59@30.5,60.4 30.5,61.1 30.65,61.25 v1(30.65,61.75) ; U21.54@32.5,60.4 32.5,61.4 v1(32.6,61.5) ; v1(34.1,51.5) U21.31@34.1,52.6 ; U21.34@35.4,53.9 35.91,53.9 36.11,53.7 v1(36.8,53.7) ; U21.42@35.4,57.1 36.3,57.1 36.5,56.9 v1(36.8,56.9)
  L1 - TOP w0.4: v1(28.075,52.15) U21.17@28.42,52.495
  L1 - TOP w0.5: R18.1@41.9,78 41.9,78.8 ; v1(42.1,79) v1(42.9,79) 43.1,78.8 R18.1@43.1,78
  L1 - TOP w0.7: FB19.1@25.4,63.1 v1(25.4,64.1) v1(25.4,64.6)
  L1 - TOP w1: 30.2,82.6 30.5,82.9 32.4,82.9 35,82.9 38.7,79.2 40.9,79.2 41.9,79.2 42.5,79.2 42.7,79.2
  L3 - SIG w0.4: 36,53.7 v1(36.8,53.7) ; 36.3,57.2 36.6,56.9 v1(36.8,56.9)
  L3 - SIG w0.5: v1(59.4,34.5) 60.2,35.3 61.6,35.3 63,36.7 v1(66.2,36.7)
  L3 - SIG w1: 36.5,64.2 36.5,67.7 36.05,68.15 36.05,76.15 39.1,79.2 41.3,79.2 42.7,79.2
  L5 - VCC w0.5: v1(42.1,79) v1(42.9,79)
  L5 - VCC w1: 35.95,69.8 35.95,76.05 39.1,79.2 42.7,79.2
  L5 - VCC w1.5: 35.95,69.8 35.95,68.75 40.6,64.1 40.6,55.1 47.4,48.3 47.4,45 49.1,43.3 49.1,39.7 53.45,35.35 55.05,35.35 55.9,34.5 v1@59.2,34.5
  L6 - BOT w0.4: v1(28.075,52.15) C203.2@29.1,52.15 ; v1(30.65,61.75) 30.65,61 C212.2@30.8,60.85 ; C205.2@33.9,52.125 34.1,51.925 v1(34.1,51.5) ; C207.2@35.85,53.7 v1(36.8,53.7) ; C209.2@35.85,57.1 35.925,57.025 35.8,56.9 v1(36.8,56.9) ; v1(55.2,35.8) FB1.1@55.2,36.5
  L6 - BOT w0.5: v1(32.6,61.5) 32.6,61.4 33,61 C211.2@33,60.85 ; C188.2@34.8,64 C188.2@34.9,64 v1(35.6,64) ; C193.2@34.85,65.3 v1(35.5,65.3) ; v1(59.4,34.5) 59.6,34.7 R19.1@59.6,37.1 ; FB2.1@65.7,37.2 v1(66.2,36.7)
  other v1: 41.3,79 40.9,79.4 41.7,79.4 42.5,79.4
1V35: C14.1 L2.2 R17.1 U2.16 | length 9.6
  L1 - TOP w0.5: 33.7,75.4 34,75.7 34,76.4 34,76.6 ; 35,75.5 R17.1@35,76.4 34.2,76.4 34,76.6 ; R17.1@35,77.6 34.2,77.6 34,77.4 34,76.6
  L1 - TOP w1.5: 30.7,74.8 32.3,74.8 33.7,74.8 34.5,75.6 34.5,75.9
2V5_LAN: C157.2 C168.2 C170.2 C172.2 C175.2 C245.2 U19.3 U19.6 U19.9 U19.12 U19.53 | length 19.5
  L1 - TOP w0.25: v1(23.705,34.85) U19.9@24.6,34.85 ; v1(23.705,36.35) U19.6@24.6,36.35 ; v1(23.705,37.85) U19.3@24.6,37.85 ; v1(23.8,33.35) U19.12@24.6,33.35 ; U19.53@26.65,39.4 v1(26.65,41.875)
  L6 - BOT w0.25: v1(23.705,34.85) 24.345,34.85 C172.2@24.35,34.855 ; v1(23.705,36.35) 24.345,36.35 C170.2@24.35,36.355 ; v1(23.705,37.85) 24.345,37.85 C168.2@24.35,37.855 ; v1@23.8,33.445 24.173,33.818 C175.2@24.173,33.878 ; 24.35,35.495 24.35,35.555 ; 24.35,36.995 24.35,37.055 ; 24.35,38.495 24.35,38.555
  L6 - BOT w0.5: 24.35,34.055 24.35,34.855 24.35,35.495 ; 24.35,35.555 24.35,36.355 24.35,36.995 ; 24.35,37.055 24.35,37.855 24.35,38.495 ; 24.35,38.555 24.35,40.905 25.32,41.875 v1(26.65,41.875)
  L6 - BOT w0.7: C245.2@22.779,40.905 24.15,40.905 C157.2@24.2,40.855
3V3: C12.1 C20.2 C21.2 C52.2 C58.2 C59.2 C78.2 C85.2 C92.2 C98.2 C109.2 C122.2 C123.2 C126.2 C127.2 C128.2 C133.2 C134.2 C155.2 C156.2 C158.2 C161.2 C163.2 C167.1 C169.2 C171.2 C173.2 C176.2 C182.2 C184.2 C186.2 C191.2 C202.2 C204.2 C206.2 C208.2 C210.2 C217.2 C218.2 C219.2 C220.2 C221.2 C223.2 C224.2 C225.2 C228.2 C230.2 C235.2 C241.2 C247.2 C274.2 C275.2 C277.2 C280.2 C301.1 C302.2 D1.1 D2.1 D9.1 FB17.1 FB22.1 FB23.1 FB24.1 J10.11 J10.13 J18.1 J26.1 L1.2 LD5.2 R1.2 R2.2 R15.1 R16.1 R23.2 R24.2 R42.2 R43.2 R44.2 R45.2 R46.2 R47.2 R80.2 R83.2 R84.2 R88.2 R91.1 R97.2 R98.2 R106.1 R107.2 R109.2 R110.2 R113.2 R131.2 R132.2 R134.2 R150.2 R151.2 R153.1 R156.1 R158.1 R159.1 R160.1 R161.2 R165.2 R166.1 R167.2 R171.2 R172.1 R176.2 R177.2 R179.2 R211.2 R212.2 R213.2 R229.1 R230.1 R231.1 R249.2 R257.2 R258.2 R263.2 R264.2 R265.1 U2.9 U3.B2 U5.5 U7.8 U9.6 U10.6 U11.6 U12.5 U15.10 U15.15 U15.23 U15.29 U15.36 U18.5 U19.13 U19.19 U19.25 U19.42 U19.44 U19.45 U19.54 U20.5 U21.23 U21.36 U21.38 U21.51 U21.57 U22.5 U23.5 U24.5 U24.7 U24.14 U24.20 U24.32 U24.37 U24.47 U25.8 U29.8 U30.8 U32.12 U33.8 U34.8 U35.5 U36.5 Y3.4 Y5.1 Y5.4 Y6.1 Y6.4 Y7.1 Y7.4 Y9.4 Y12.4 | length 229.3
  L1 - TOP w0.1: U3.B2@39.25,73.25 39.5,73 39.5,72.6 39.9,72.2 v1(39.9,70.2)
  L1 - TOP w0.2: v1@49.875,61.8 v1(49.9,61.8) ; v1@49.875,66.3 v1(49.9,66.3)
  L1 - TOP w0.25: v1(23.7,32.6) 23.95,32.85 U19.13@24.6,32.85 ; v1(26.1,41.2) 26.15,41.15 U19.54@26.15,39.4 ; v1(27.15,31.15) U19.19@27.15,31.8 ; v1(30.15,30.75) U19.25@30.15,31.8 ; U19.45@30.65,39.4 30.65,40.25 v1(30.7,40.3) ; v1(30.9,51.5) U21.23@30.9,52.6 ; U19.44@31.15,39.4 31.15,40.15 v1(31.3,40.3) ; v1(31.2,61.5) 31.3,61.4 U21.57@31.3,60.4 ; U19.42@32.2,38.85 v1(32.2,39.3) ; U21.51@33.7,60.4 33.7,60.9 33.9,61.1 34.9,61.1 v1(35.1,60.9) ; U21.36@35.4,54.7 35.91,54.7 36.11,54.5 v1(36.8,54.5) ; U21.38@35.4,55.5 36.1,55.5 36.5,55.1 v1(36.8,55.1)
  L1 - TOP w0.3: 24.1,75.7 24.1,76.5 U2.9@25.25,76.5 ; R132.2@34.65,33.155 v1(35.4,33.155) ; 39.9,67.8 v1(39.9,70.2) ; v1(44.05,22.25) C122.2@44.73,22.25 45.555,22.25 46.155,22.85 Y5.4@48.055,22.85 ; v1(50.88,21.675) 51.505,22.3 U15.36@52.08,22.3 ; v1(51.15,25.925) 51.275,25.8 U15.29@52.08,25.8 ; U15.23@54.83,27.05 v1(54.83,28.825) ; R110.2@56.4,79.4 v1(56.4,80.438) ; U15.10@57.58,22.3 57.58,21.22 v1(57.6,21.2) ; U15.15@57.58,24.8 v1(58.78,24.8) ; v1(106.45,45.75) U24.32@107.3,45.75 ; v1(106.45,51.75) U24.20@107.3,51.75 ; U24.14@108.95,53.9 v1(108.95,54.75) ; v1(109.95,44.337) U24.37@109.95,45.187 ; U24.7@112.45,53.9 v1(112.45,54.75) ; U24.5@113.45,53.9 v1(113.45,54.75) ; C228.2@114.95,42.8 U24.47@114.95,45.1
  L1 - TOP w0.4: J18.1@30.29,8.632 v1(30.29,10.664) ; C274.2@42.55,54.7 v1(42.55,55.3) 42.55,55.75 U30.8@42.6,55.8 ; C123.2@44.445,28.695 44.45,28.7 U12.5@46.045,28.7 v1(47,28.7) ; C98.2@48.2,58.05 48.25,58 v1(48.8,58) U11.6@49.55,58 ; C109.2@48.2,62.85 48.25,62.8 v1(48.8,62.8) U10.6@49.55,62.8 ; C92.2@48.2,67.35 48.25,67.3 v1(48.8,67.3) U9.6@49.55,67.3 ; v1(48.8,27.4) R113.2@49.55,27.4 ; v1(50.8,48) 50.8,48.9 R46.2@51,49.1 51,49.7 R43.2@51.8,50.5 ; R166.1@57.25,37.1 57.25,37.65 v1(57.475,37.875) ; C52.2@64.1,36.45 v1(64.1,35.7) 65.4,35.7 Y3.4@65.575,35.875 ; R106.1@97.775,27.75 97.8,27.775 v1(97.8,28.6) ; 103.775,30.8 v1@103.775,31.438 ; FB22.1@122.5,50 v1(122.5,50.9)
  L1 - TOP w0.5: v1(23.1,68.5) C182.2@23.1,67.65 24.425,67.65 Y7.1@24.7,67.925 Y7.4@26.3,67.925 ; v1(25.4,44.5) 25.405,44.505 LD5.2@26.8,44.505 ; C167.1@31.95,21.5 32.125,21.5 33.505,22.88 U33.8@33.505,23.575 ; v1(32,20.8) C167.1@32,21.35 ; Y6.4@32.1,41.355 v1(33.05,41.355) 35.05,41.355 C155.2@35.5,41.805 v1(36.195,41.805) ; R131.2@34.2,31.65 v1(34.85,31.65) ; v1(34.8,74.1) R23.2@35.55,74.1 ; R15.1@35,69.4 34.2,69.4 34,69.6 34,70.4 34.2,70.6 R15.1@35,70.6 ; v1(35.5,66.5) 35.5,67.694 35.606,67.8 ; R16.1@41.9,69 41.9,68.2 42.1,68 42.9,68 43.1,68.2 R16.1@43.1,69 ; R109.2@48.862,78.8 v1(48.862,79.638) ; R107.2@50.162,78.788 v1(50.162,79.638) ; R80.2@102.95,30.8 103.775,30.8 104.35,30.8 C78.2@104.375,30.775 ; R88.2@104,37.05 v1(104.65,37.05) ; U5.5@104.335,29.7 104.335,30.685 C78.2@104.45,30.8 ; v1(105,42.5) 104.4,43.1 C221.2@103.95,43.1 103.98,43.07 U23.5@103.98,41.65 104.18,41.45 R167.2@105.5,41.45 ; R84.2@106,33.85 106.038,33.888 v1@106.8,33.888 ; C85.2@106,36.75 106.05,36.7 106.15,36.8 v1(106.8,36.8) ; R83.2@106.5,27.65 v1(107.175,27.65) ; v1(107.7,37.1) U7.8@108.4,37.1 ; v1(108.3,63.4) C218.2@109.15,63.4 ; v1(110.325,41.4) 111.1,41.4 R171.2@111.125,41.425 ; R172.1@113.8,42.45 114.211,42.45 114.561,42.8 114.95,42.8 C228.2@115,42.8 115,42.55 v1(115.5,42.05) 115.8,41.75 D9.1@115.8,41.1 ; v1(115.15,63.4) C224.2@115.15,62.4 115.8,62.4 ; R165.2@116.45,62.4 115.8,62.4 ; Y9.4@116.625,59.2 115.8,60.025 115.8,62.4 ; v1(119.4,3.4) R258.2@119.4,4.35 ; v1(121.1,3.4) R257.2@121.1,4.35 ; Y12.4@124.65,10.35 124.875,10.125 v1(125.663,10.125) C277.2@126.45,10.125 ; U32.12@130.3,26.655 130.25,26.705 C301.1@130.25,28.5 ; v1(130.8,28.5) C301.1@130.25,28.5 ; v1(130.8,29.8) C302.2@129.985,29.8 130.25,29.535 C301.1@130.25,28.5
  L1 - TOP w0.7: FB17.1@23.9,63.1 v1(23.9,64.1) v1(23.9,64.6)
  L1 - TOP w1: L1.2@23.8,73.65 23.8,72.1 25.15,70.75 C12.1@25.15,70.2 ; C12.1@25.3,70 v1(26.2,70) v1(27,70) v1(28,70) v1(29,70) v1(30,70) v1(30.8,70) v1(31.6,70) v1(32.5,70) v1(33.5,70) 33.725,70 33.725,68.675 34.6,67.8 35.606,67.8 39.9,67.8 42.6,67.8
  L6 - BOT w0.25: v1(23.7,32.6) 24.305,32.6 C176.2@24.35,32.555 ; C171.2@30.3,39.6 C171.2@30.3,39.7
  L6 - BOT w0.3: C20.2@39.85,68.9 39.85,70.15 v1(39.9,70.2) ; v1(50.88,21.675) C126.2@51.73,21.675 ; v1(51.15,25.925) 51.155,25.925 C128.2@51.73,25.35 ; v1(54.83,28.825) 54.83,28.45 C127.2@55.88,27.4 ; C134.2@55.9,21.15 57.55,21.15 v1(57.6,21.2) ; C133.2@58.05,24.3 58.28,24.3 v1(58.78,24.8) ; v1(106.45,45.75) 106.7,45.75 C220.2@107.35,46.4 ; v1(106.45,51.75) 107.2,51.75 C230.2@107.35,51.6 ; C223.2@108.8,53.75 108.95,53.9 v1(108.95,54.75) ; C219.2@112.4,53.55 112.45,53.6 v1(112.45,54.75) ; v1(113.45,54.75) 113.8,54.75 C225.2@114.8,53.75 ; C225.2@114.7,53.65 C225.2@114.8,53.55
  L6 - BOT w0.4: v1(20.9,28.7) R151.2@21.75,28.7 ; v1(20.903,29.8) R150.2@21.753,29.8 ; v1(20.903,30.9) R134.2@21.753,30.9 ; v1(24.2,4.5) 24.25,4.45 R213.2@26.44,4.45 R212.2@28.99,4.45 R211.2@30.265,4.45 31.15,4.45 v1(31.2,4.5) ; C247.2@25.1,39.65 26.1,40.65 C158.2@26.1,40.7 ; R156.1@28.55,48.6 28.55,47.8 v1(28.65,47.7) ; C171.2@30.3,39.7 30.3,39.9 v1(30.7,40.3) ; v1(30.9,51.5) C210.2@30.9,52.15 ; v1(31.2,61.5) 31.3,61.5 C202.2@31.888,60.913 ; v1(31.3,40.3) 31.5,40.1 C161.2@31.5,39.7 ; v1(32.2,39.3) 32.505,39.605 C169.2@32.7,39.605 ; C156.2@34.3,40.55 35.7,40.55 U18.5@35.8,40.45 35.9,40.35 v1(35.9,39.7) ; C208.2@35.85,54.7 35.975,54.575 35.9,54.5 v1(36.8,54.5) ; C206.2@35.85,55.7 36.45,55.1 v1(36.8,55.1) ; C184.2@37.65,63.4 v1(37.65,62.725) 37.65,62.05 U20.5@37.75,61.95 ; v1(38.5,55) 39.761,55 40.55,55.789 R153.1@40.55,56.2 R177.2@40.55,57.4 ; C275.2@45.85,54.6 C275.2@45.85,54.7 v1(45.85,55.3) U29.8@45.85,55.8 ; R44.2@49.3,69.4 48.5,70.2 v1(48.5,70.6) 48.5,71 R47.2@49.3,71.8 ; v1(49.9,66.3) 49.9,67.15 R91.1@50.05,67.3 ; R97.2@50.05,61 49.9,61.15 v1(49.9,61.8) 49.9,62.65 R98.2@50.05,62.8 ; R45.2@50.1,52.7 50.7,53.3 v1(50.7,53.4) 50.7,54 R42.2@50.9,54.2 ; v1(94.35,37.5) C59.2@94.35,38.3 U36.5@95.8,38.3 ; v1(94.55,40.35) C58.2@94.55,41 U35.5@95.796,41
  L6 - BOT w0.5: v1(2.2,61) R160.1@2.2,61.9 ; R159.1@2.2,68.3 v1(2.2,69.2) ; v1(2.2,80) R158.1@2.2,80.9 ; R161.2@2.3,49.3 v1(2.3,50.2) ; v1(6.62,75.85) R264.2@7.52,75.85 ; R263.2@7.52,71.75 v1(7.52,72.65) ; v1(7.55,57.5) R265.1@8.45,57.5 ; R2.2@21.75,79.9 v1(21.75,80.6) R1.2@21.75,81.3 ; C158.2@26.1,40.7 v1@26.1,41.155 ; C280.2@26.3,31.55 26.75,31.55 v1(27.15,31.15) 27.15,30.75 27.65,30.25 C163.2@27.8,30.25 ; v1(30.15,30.75) 30.15,31.25 C173.2@30.4,31.5 ; C186.2@34.8,62.6 C186.2@34.9,62.6 v1(35.6,62.6) ; v1(34.8,74.1) R24.2@35.55,74.1 ; C191.2@34.85,66.5 v1(35.5,66.5) ; v1(35.1,60.9) 35.15,60.85 C204.2@35.15,60 ; D1.1@40.5,47.1 40.8,47.1 41.5,46.4 v1(41.9,46.4) 41.95,46.35 D2.1@41.95,44.65 ; v1(41.1,44.2) 41.5,44.2 D2.1@41.95,44.65 ; v1(42.8,44.2) 42.4,44.2 D2.1@41.95,44.65 ; U34.8@48.2,81.995 48.35,81.845 C241.2@48.35,80.5 48.35,80.089 48.389,80.089 48.4,80.1 ; 48.4,80.1 v1(48.862,79.638) ; R229.1@59.4,79.8 59.5,79.9 v1(59.5,81) ; R230.1@88.4,79.8 v1(88.4,81.4) ; v1(107.5,56.7) C217.2@108.55,56.7 U22.5@108.55,58.3 ; v1(110.325,41.4) R179.2@111.15,41.4 ; v1(113.625,57.525) FB23.1@114.65,57.525 ; R176.2@114.25,41.4 114.85,41.4 v1(115.5,42.05) 114.85,42.7 FB24.1@114.7,42.7 ; U25.8@115.905,39.8 116.355,40.25 v1(116.7,40.25) C235.2@117.4,40.25 ; R231.1@117.4,79.8 v1(117.4,81.4) ; R249.2@140.65,10.1 v1(141.5,10.1)
  other v1: 103.775,31.45 106.8,33.9
AVDDH: C185.2 C190.2 C195.2 C197.2 C199.2 FB17.2 U21.1 U21.8 U21.15 | length 21.3
  L1 - TOP w0.25: v1(25.5,53.875) 26.625,53.875 26.65,53.9 U21.15@27.6,53.9 ; v1@25.5,56.675 26.6,56.675 26.65,56.7 U21.8@27.6,56.7 ; v1(25.5,59.5) U21.1@27.6,59.5
  L1 - TOP w0.5: FB17.2@23.9,61.5 v1@24.595,60.805
  L5 - VCC w0.5: v1(25.5,53.875) v1(25.5,56.75) v1(25.5,59.5)
  L6 - BOT w0.5: C185.2@23.9,61.5 24.65,60.75 C190.2@24.65,59.8 25.2,59.8 v1(25.5,59.5) 26.95,59.5 C199.2@27.15,59.7 ; v1(25.5,53.875) 26.375,53 C195.2@27.05,53 ; v1(25.5,56.75) 25.85,56.4 C197.2@27.15,56.4
  other v1: 24.6,60.8
AVDDL: C187.2 C192.2 C194.2 C196.2 C198.2 C200.2 C201.2 FB19.2 U21.4 U21.7 U21.11 U21.14 U21.60 | length 26.2
  L1 - TOP w0.25: v1(26.2,54.3) U21.14@27.6,54.3 ; v1(26.2,55.5) U21.11@27.6,55.5 ; v1(26.2,57.1) U21.7@27.6,57.1 ; v1(26.2,58.3) U21.4@27.6,58.3 ; U21.60@30.1,60.4 v1(30.1,61.4)
  L1 - TOP w0.6: C192.2@24.65,59.8 25.4,60.55 v1(25.4,60.8) FB19.2@25.4,61.5
  L3 - SIG w0.5: v1(26.2,54.3) v1(26.2,55.5) v1(26.2,57.1) v1(26.2,58.3) 26.2,60 v1(25.4,60.8) 26,61.4 v1(30.1,61.4)
  L6 - BOT w0.4: C201.2@29.7,60.85 29.7,61 v1(30.1,61.4)
  L6 - BOT w0.5: v1(25.4,60.8) C187.2@25.4,61.5 ; v1(26.2,54.3) 26.3,54.2 C200.2@27.15,54.2 ; v1(26.2,55.5) 26.4,55.3 C196.2@27.15,55.3 ; v1(26.2,57.1) 26.6,57.5 C198.2@27.15,57.5 ; v1(26.2,58.3) 26.5,58.6 C194.2@27.15,58.6
  L6 - BOT w0.6: C187.2@25.4,61.5 C187.2@25.5,61.6
CMD_PWR1: U15.12 U16.4 | length 36.1
  L1 - TOP w0.125: U15.12@57.58,23.3 58.892,23.3 59.5,22.692 v1(59.5,20.5)
  L6 - BOT w0.125: U16.4@43.355,1.805 44.767,3.217 53.346,3.217 53.9,3.772 53.9,17.134 56.266,19.5 58.5,19.5 v1(59.5,20.5)
CMD_PWR2: U15.16 U16.1 | length 37.5
  L1 - TOP w0.125: U15.16@57.58,25.3 59.028,25.3 60.5,23.828 v1(60.5,19.8)
  L6 - BOT w0.125: U16.1@47.165,1.31 54.91,1.31 55.6,2 55.6,17.196 56.808,18.405 59.105,18.405 v1(60.5,19.8)
CMD_PWR3: U15.18 U17.4 | length 47
  L1 - TOP w0.125: U15.18@57.58,26.3 59.298,26.3 61.5,24.098 v1(61.5,20)
  L6 - BOT w0.125: v1(61.5,20) 63.2,18.3 72.1,18.3 73.003,17.397 73.003,3.762 72.441,3.2 63.9,3.2 62.495,1.795 U17.4@62.495,1.3
CMD_PWR4: U15.20 U17.1 | length 50.1
  L1 - TOP w0.125: U15.20@56.33,27.05 56.33,27.612 56.532,27.813 59.055,27.813 63,23.868 v1(63,20.5)
  L6 - BOT w0.125: v1(63,20.5) 63.9,20.5 64.8,19.6 73.05,19.6 75.1,17.55 75.1,2.3 74.1,1.3 U17.1@66.305,1.3
CON_JTAG_TCK: J18.4 R212.1 U31.9 | length 25.9
  L1 - TOP w0.125: U31.9@24.75,23.35 24.75,23.65 25.05,23.95 26.75,23.95 27.3,23.4 27.3,19.5 v1(27.8,19) ; J18.4@29,4.548 J18.4@29.02,4.568 v1(29.02,6.6) ; J18.4@29.01,4.561 J18.4@29.01,5.64
  L6 - BOT w0.125: v1(27.8,19) 30,16.8 30,12.2 29.6,11.8 29.6,10 29.02,9.42 v1(29.02,6.6) 29.02,5.38 R212.1@28.99,5.35
CON_JTAG_TDI: J18.8 R213.1 U31.1 | length 23.3
  L1 - TOP w0.125: v1(23.1,19.4) 23.25,19.55 U31.1@23.25,20.45 ; J18.8@26.45,4.541 26.47,4.561 J18.8@26.47,5.605 ; J18.8@26.48,4.568 v1(26.48,6.6)
  L6 - BOT w0.125: v1(23.1,19.4) 23.3,19.4 24.6,18.1 27,18.1 29,16.1 29,13.8 26.48,11.28 v1(26.48,6.6) 26.48,5.39 R213.1@26.44,5.35
CON_JTAG_TDO: J18.6 U31.5 | length 20.6
  L1 - TOP w0.125: v1(25.45,19.45) U31.5@25.45,21.15 ; J18.6@27.74,4.561 J18.6@27.74,5.635 ; J18.6@27.75,4.568 v1(27.75,6.6)
  L6 - BOT w0.125: v1(25.45,19.45) 26.353,18.547 27.353,18.547 29.5,16.4 29.5,12.8 28.3,11.6 28.3,9.7 27.75,9.15 v1(27.75,6.6)
CON_JTAG_TMS: J18.2 R211.1 U31.13 | length 26.7
  L1 - TOP w0.125: v1(21.8,22.75) 21.9,22.65 U31.13@22.55,22.65 ; J18.2@30.275,4.785 J18.2@30.28,4.79 ; J18.2@30.28,5.595 J18.2@30.28,4.79 ; v1(30.29,6.6) 30.29,4.8 J18.2@30.28,4.79
  L6 - BOT w0.125: v1(21.8,22.75) 25.25,22.75 30.7,17.3 30.7,8.9 30.29,8.49 v1(30.29,6.6) 30.29,5.375 R211.1@30.265,5.35
DDR_A0: U4.F12 U6.N3 U8.N3 | length 57.6
  L1 - TOP w0.125: U4.F12@66.4,52.4 v1(66.8,52.8) ; v1(89.6,63.2) 89.85,63.2 91,62.05 U8.N3@91,61.1 ; v1(90.7,44) 90.9,43.8 U6.N3@90.9,43.1
  L4 - SIG w0.125: v1(66.8,52.8) 67.2,53.2 67.2,53.775 67.425,54 68.225,54 68.6,54 68.8,54.2 68.8,54.575 69.025,54.8 69.55,54.8 70.55,55.8 71.957,55.8 73.357,57.2 76.036,57.2 77.736,55.5 80.25,55.5 80.45,55.3 80.45,54.7 80.65,54.5 81.25,54.5 81.45,54.7 81.45,55.3 81.65,55.5 82.95,55.5 83.1,55.35 83.1,55 83.2,54.9 83.95,54.9 84.15,54.7 84.15,54.2 84.35,54 84.65,54 84.85,54.2 84.85,55.3 85.05,55.5 88.2,55.5 88.35,55.35 88.35,54.885 88.535,54.7 88.8,54.7 88.96,54.86 88.96,55.31 89.15,55.5 89.5,55.5 89.7,55.3 89.7,54.95 89.85,54.8 v1(90.2,54.8)
  L6 - BOT w0.125: v1(89.6,63.2) 89.4,63 89.4,61.45 89.65,61.2 89.957,61.2 90.25,60.907 90.25,58.2 89.45,57.4 89.45,55.55 v1(90.2,54.8) 90.4,54.6 90.4,46.5 89.85,45.95 89.85,44.9 v1@90.75,44
DDR_A1: U4.C17 U6.P7 U8.P7 | length 57.6
  L1 - TOP w0.125: U4.C17@70.4,54.8 73.1,54.8 73.4,54.5 79.1,54.5 79.95,53.65 79.95,53.3 80.45,52.8 ; 80.45,52.8 84.2,52.8 84.65,53.25 84.65,54.806 85.343,55.499 86.957,55.499 87.556,54.9 89.363,54.9 90.25,54.013 90.25,53.5 90.75,53 91.85,53 92.55,53.7 94.3,53.7 94.75,54.15 94.75,55.5 94.55,55.7 94.15,55.7 93.95,55.5 v1(93.95,54.4) ; v1(91.4,63.9) U8.P7@91.8,64.3 ; U6.P7@91.7,46.3 91.707,46.3 92.607,45.4 92.6,45.393 92.6,44.9 92.8,44.7 93.2,44.7 93.4,44.9 v1(93.4,45.4)
  L6 - BOT w0.125: v1(91.4,63.9) 93.043,63.9 94.45,62.493 94.45,57.9 93.95,57.4 v1(93.95,54.4) 93.95,45.95 v1(93.4,45.4)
